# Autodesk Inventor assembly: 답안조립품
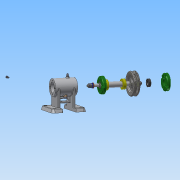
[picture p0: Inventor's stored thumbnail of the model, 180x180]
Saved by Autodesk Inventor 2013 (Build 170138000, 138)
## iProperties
Created: 2016-07
Part Number: 답안조립품
Document SubType Name: Assembly
Designer: Administrator
Author: Administrator
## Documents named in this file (16)
- C:\Users\Administrator\Desktop\460708V1014\답안조립품.iam
- C:\Users\Administrator\Desktop\460708V1014\본체.ipt
- C:\Users\Administrator\Desktop\460708V1014\V벨트풀리.ipt
- C:\Users\Administrator\Desktop\460708V1014\너트 M 8.ipt
- C:\Users\Administrator\Desktop\460708V1014\니플 M 6 x 0.75.ipt
- C:\Users\Administrator\Desktop\460708V1014\베어링 15 x 32 x 9.ipt
- C:\Users\Administrator\Desktop\460708V1014\볼트 M 6 x 8.ipt
- C:\Users\Administrator\Desktop\460708V1014\볼트 M4 x 12.ipt
- C:\Users\Administrator\Desktop\460708V1014\스퍼기어.ipt
- C:\Users\Administrator\Desktop\460708V1014\스프링와셔 8.ipt
- C:\Users\Administrator\Desktop\460708V1014\오일 실 15 25 7.ipt
- C:\Users\Administrator\Desktop\460708V1014\와셔 6x11.5.ipt
- C:\Users\Administrator\Desktop\460708V1014\와셔 8x17.ipt
- C:\Users\Administrator\Desktop\460708V1014\축.ipt
- C:\Users\Administrator\Desktop\460708V1014\키 3 x 3 x 12.ipt
- C:\Users\Administrator\Desktop\460708V1014\커버.ipt
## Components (4 placed, 3 different names)
1. V벨트풀리:1
2. KS B 2023 6002 - 15 x 32 x 9:1
3. ISO 4762 M4 x 12:1
4. KS B 2023 6002 - 15 x 32 x 9:2
